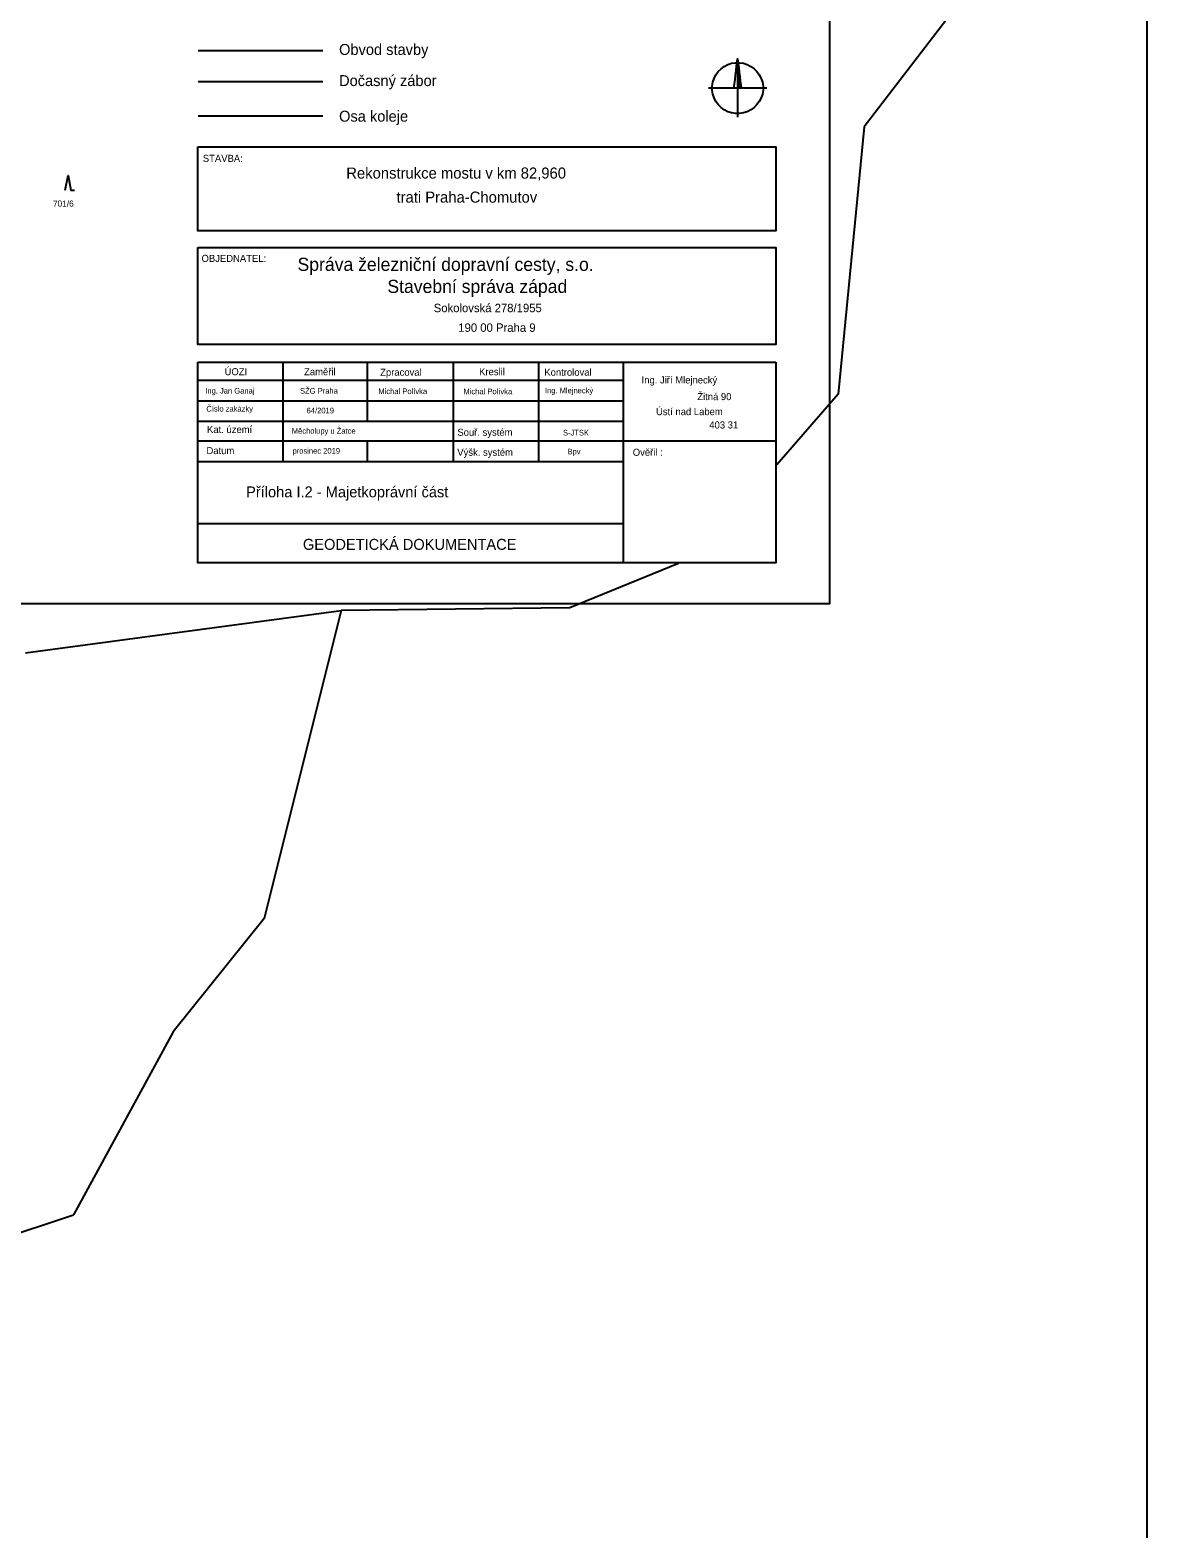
# Model space of a CAD drawing. Extents: x -801907 to -800293, y -1017000 to -1015684.
# Drawn here: x -800931.6 to -800625, y -1017000 to -1016586 of the extents above; entities that cross this region are included whole.
import ezdxf

# ---------------------------------------------------------------- set-up
doc = ezdxf.new("R2010")
doc.units = 0
for name, color, linetype in [('Default', 7, 'Continuous'), ('KLADY_ZMVM', 7, 'Continuous'), ('KN_HRANICE', 7, 'Continuous'), ('KN_KULTURY', 7, 'Continuous'), ('KN_PARCELY', 7, 'Continuous'), ('LEGENDA', 7, 'Continuous'), ('tabulka', 7, 'Continuous')]:
    doc.layers.add(name, color=color, linetype=linetype)

# ---------------------------------------------------------------- blocks, each defined once
blk = doc.blocks.new('308')
at = {"layer": 'Default'}
blk.add_lwpolyline([(-0.75, 0), (0, 4), (0.75, 0), (1.75, 0)], dxfattribs=at)
blk = doc.blocks.new('SEVER')
at = {"layer": 'Default'}
for points in [[(5.5, 69.8), (16.3, 68.1), (26.7, 64.7), (36.5, 59.7), (45.4, 53.2), (53.2, 45.4), (59.7, 36.5), (64.7, 26.7), (68.1, 16.3), (69.8, 5.5), (69.8, -5.5), (68.1, -16.3), (64.7, -26.7), (59.7, -36.5), (53.2, -45.4), (45.4, -53.2), (36.5, -59.7), (26.7, -64.7), (16.3, -68.1), (5.5, -69.8), (-5.5, -69.8), (-16.3, -68.1), (-26.7, -64.7), (-36.5, -59.7), (-45.4, -53.2), (-53.2, -45.4), (-59.7, -36.5), (-64.7, -26.7), (-68.1, -16.3), (-69.8, -5.5), (-69.8, 5.5), (-68.1, 16.3), (-64.7, 26.7), (-59.7, 36.5), (-53.2, 45.4), (-45.4, 53.2), (-36.5, 59.7), (-26.7, 64.7), (-16.3, 68.1), (-5.5, 69.8), (5.5, 69.8)], [(-10, 0), (-8.5, 12), (-7, 24), (-5.5, 36), (-4, 48), (-2.5, 60), (-1, 72), (0, 80), (1.5, 68), (3, 56), (4.5, 44), (6, 32), (7.5, 20), (9, 8), (10, 0), (9.2, 0.8), (9.2, 5.6), (8.4, 12), (8.4, 0.8), (7.6, 0.8), (7.6, 13.5), (7.6, 18.4), (6.8, 24.8), (6.8, 12.1), (6.8, 0.8), (6, 0.8), (6, 13.5), (6, 26.2), (6, 31.2), (5.2, 36.8), (5.2, 24.1), (5.2, 11.4), (5.2, 0.8), (4.4, 0.8), (4.4, 13.5), (4.4, 26.2), (4.4, 38.9), (4.4, 43.2), (3.6, 50.4), (3.6, 37.7), (3.6, 25), (3.6, 12.3), (3.6, 0.8), (2.8, 0.8), (2.8, 13.5), (2.8, 26.2), (2.8, 38.9), (2.8, 51.6), (2.8, 56), (2, 63.2), (2, 50.5), (2, 37.8), (2, 25.1), (2, 12.4), (2, 0.8), (1.2, 0.8), (1.2, 13.5), (1.2, 26.2), (1.2, 38.9), (1.2, 51.6), (1.2, 64.3), (1.2, 69.6), (0.4, 76), (0.4, 63.3), (0.4, 50.6), (0.4, 37.9), (0.4, 25.2), (0.4, 12.5), (0.4, 0.8)], [(0, 80), (0, 67.3), (0, 54.6), (0, 41.9), (0, 29.2), (0, 16.5), (0, 3.8), (0, -8.9), (0, -21.6), (0, -34.3), (0, -47), (0, -59.7), (0, -72.4), (0, -80)], [(80, 0), (67.3, 0), (54.6, 0), (41.9, 0), (29.2, 0), (16.5, 0), (3.8, 0), (-8.9, 0), (-21.6, 0), (-34.3, 0), (-47, 0), (-59.7, 0), (-72.4, 0), (-80, 0)]]:
    blk.add_lwpolyline(points, dxfattribs=at)

msp = doc.modelspace()

# ---------------------------------------------------------------- linework, layer by layer
at = {"layer": 'KLADY_ZMVM'}
msp.add_lwpolyline([(-800625, -1016000), (-800625, -1016500), (-800625, -1017000)], dxfattribs=at)
at = {"layer": 'KN_HRANICE'}
for p, q in [((-800672.38, -1016573.21), (-800702.65, -1016612.58)), ((-800702.65, -1016612.58), (-800709.73, -1016685.98)), ((-800709.73, -1016685.98), (-800726.57, -1016705.41)), ((-800753.62, -1016732.42), (-800783.37, -1016744.64)), ((-800932.89, -1016756.98), (-800846.15, -1016745.38)), ((-800846.15, -1016745.38), (-800867.3, -1016829.9)), ((-800783.37, -1016744.64), (-800846.15, -1016745.38)), ((-800867.3, -1016829.9), (-800892.3, -1016861.04)), ((-800892.3, -1016861.04), (-800919.72, -1016911.28)), ((-800966.67, -1016927.02), (-800919.72, -1016911.28))]:
    msp.add_line(p, q, dxfattribs=at)
at = {"layer": 'LEGENDA'}
for p, q in [((-800885.41, -1016591.57), (-800851.22, -1016591.57)), ((-800885.41, -1016600.11), (-800851.22, -1016600.11)), ((-800885.41, -1016609.57), (-800851.22, -1016609.57))]:
    msp.add_line(p, q, dxfattribs=at)
msp.add_lwpolyline([(-801306.12, -1016323.56), (-800712.12, -1016323.56), (-800712.12, -1016743.56), (-801306.12, -1016743.56)], close=True, dxfattribs=at)
at = {"layer": 'tabulka'}
for p, q in [((-800885.51, -1016677.17), (-800726.85, -1016677.17)), ((-800862.22, -1016677.17), (-800862.22, -1016704.49)), ((-800839.07, -1016677.17), (-800839.07, -1016693.37)), ((-800815.47, -1016677.17), (-800815.47, -1016704.49)), ((-800792.02, -1016677.17), (-800792.02, -1016704.49)), ((-800768.72, -1016732.3), (-800768.72, -1016677.17)), ((-800885.51, -1016682.08), (-800768.72, -1016682.08)), ((-800885.51, -1016687.79), (-800768.72, -1016687.79)), ((-800885.51, -1016693.37), (-800768.72, -1016693.37)), ((-800885.51, -1016698.79), (-800726.85, -1016698.79)), ((-800839.07, -1016698.79), (-800839.07, -1016704.49)), ((-800885.51, -1016704.49), (-800768.72, -1016704.49)), ((-800885.51, -1016721.48), (-800768.72, -1016721.48))]:
    msp.add_line(p, q, dxfattribs=at)
for points in [[(-800885.51, -1016618.08), (-800726.85, -1016618.08), (-800726.85, -1016641.15), (-800885.51, -1016641.15)], [(-800885.51, -1016645.67), (-800726.85, -1016645.67), (-800726.85, -1016672.36), (-800885.51, -1016672.36)]]:
    msp.add_lwpolyline(points, close=True, dxfattribs=at)
msp.add_lwpolyline([(-800726.85, -1016677.17), (-800726.85, -1016732.3), (-800885.51, -1016732.3), (-800885.51, -1016677.17)], dxfattribs=at)

# ---------------------------------------------------------------- block references
at = {"layer": 'KN_KULTURY'}
msp.add_blockref('308', (-800921.18, -1016629.94), dxfattribs=at)
at = {"layer": 'LEGENDA', "xscale": 0.1, "yscale": 0.10000000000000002}
msp.add_blockref('SEVER', (-800737.36, -1016601.93), dxfattribs=at)

# ---------------------------------------------------------------- texts
at = {"layer": 'KN_PARCELY'}
msp.add_text('701/6', height=1.7, dxfattribs=at).set_placement((-800925.31, -1016634.49))
at = {"layer": 'LEGENDA'}
for s, p in [('Obvod stavby', (-800846.77, -1016592.82)), ('Dočasný zábor', (-800846.77, -1016601.37)), ('Osa koleje', (-800846.77, -1016611.14))]:
    msp.add_text(s, height=3, dxfattribs=at).set_placement(p)
at = {"layer": 'tabulka'}
for s, height, p in [('STAVBA:', 1.94, (-800884.16, -1016622.19)), ('Rekonstrukce mostu v km 82,960', 3.04, (-800844.79, -1016626.77)), ('trati Praha-Chomutov', 3.04, (-800831.01, -1016633.38)), ('OBJEDNATEL:', 1.94, (-800884.52, -1016649.65)), ('Správa železniční dopravní cesty, s.o.', 3.61, (-800858.17, -1016652.12)), ('Stavební správa západ', 3.61, (-800833.5, -1016658.18)), ('Sokolovská 278/1955', 2.32, (-800820.78, -1016663.46)), ('190 00 Praha 9', 2.32, (-800814.04, -1016668.85)), ('ÚOZI', 1.94, (-800878.2, -1016680.77)), ('Zaměřil', 1.94, (-800856.37, -1016680.77)), ('Zpracoval', 1.94, (-800835.48, -1016680.92)), ('Kreslil', 1.94, (-800808.32, -1016680.77)), ('Kontroloval', 1.94, (-800790.41, -1016680.92)), ('SŽG Praha', 1.552, (-800857.48, -1016685.83)), ('Ing. Mlejnecký', 1.552, (-800790.26, -1016685.73)), ('Ing. Jiří Mlejnecký', 1.94, (-800763.71, -1016683.03)), ('Ing. Jan Ganaj', 1.552, (-800883.5, -1016685.8)), ('Michal Polívka', 1.552, (-800835.96, -1016685.95)), ('Michal Polívka', 1.552, (-800812.62, -1016685.99)), ('Žitná 90', 1.94, (-800748.42, -1016687.61)), ('Číslo zakázky', 1.552, (-800883.2, -1016690.75)), ('64/2019', 1.552, (-800855.67, -1016691.24)), ('Ústí nad Labem', 1.94, (-800759.75, -1016691.73)), ('Kat. území', 1.94, (-800883.01, -1016696.63)), ('Měcholupy u Žatce', 1.552, (-800859.75, -1016696.83)), ('Souř. systém', 1.94, (-800814.29, -1016697.4)), ('S-JTSK', 1.552, (-800785.3, -1016697.31)), ('403 31', 1.94, (-800745.12, -1016695.39)), ('Datum', 1.94, (-800883.16, -1016702.43)), ('prosinec 2019', 1.552, (-800859.54, -1016702.32)), ('Výšk. systém', 1.94, (-800814.31, -1016702.89)), ('Bpv', 1.552, (-800784.04, -1016702.5)), ('Ověřil :', 1.94, (-800766.13, -1016702.89)), ('Příloha I.2 - Majetkoprávní část', 3, (-800872.29, -1016714.3)), ('GEODETICKÁ DOKUMENTACE ', 3, (-800856.69, -1016728.71))]:
    msp.add_text(s, height=height, dxfattribs=at).set_placement(p)

doc.saveas('drawing.dxf')
